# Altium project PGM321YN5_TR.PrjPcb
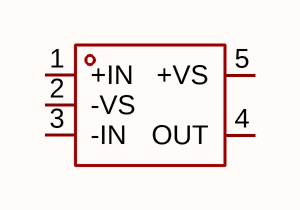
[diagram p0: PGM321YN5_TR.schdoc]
1 sheet, 1 parts. Net scope: global (net labels, ports and power ports of the same name join across sheets).

## Sheet PGM321YN5_TR.schdoc
size 127 x 101 mm

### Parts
U?  pgm321yn5/tr  [SOT-23-5_L2.9-W1.6-P0.95-LS2.8-BL]  (value not drawn)

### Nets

Not connected (* = marked no-connect by the designer): U? 1(+IN) 2(-VS) 3(-IN) 4(OUT) 5(+VS)

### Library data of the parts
U? = pgm321yn5/tr: Manufacturer: TECH PUBLIC(台舟); AddInBom: yes; ModelId: 018c57e721114987ae90467fe9f1d259; ModelTransform: 114.96,110.236,0,0,0,0,0,0,0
